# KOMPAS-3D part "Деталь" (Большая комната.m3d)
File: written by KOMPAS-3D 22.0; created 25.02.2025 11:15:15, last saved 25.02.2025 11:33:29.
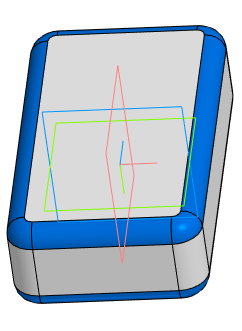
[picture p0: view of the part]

Document properties: Автор: Пользователь Windows; Полное имя файла: C:\Users\Student\Documents\Картошечка\База Сабнатика\Большая комната\Большая комната.m3d

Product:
- Part/product: Деталь
    Масса: 2.227738

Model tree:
1. Эскиз:1
2. Элемент выдавливания:1
     Расстояние 1 = 35
3. Скругление:2  (with: Элемент выдавливания:1)
     Радиус = 10
4. Скругление:1  (with: Элемент выдавливания:1)
     Радиус = 7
